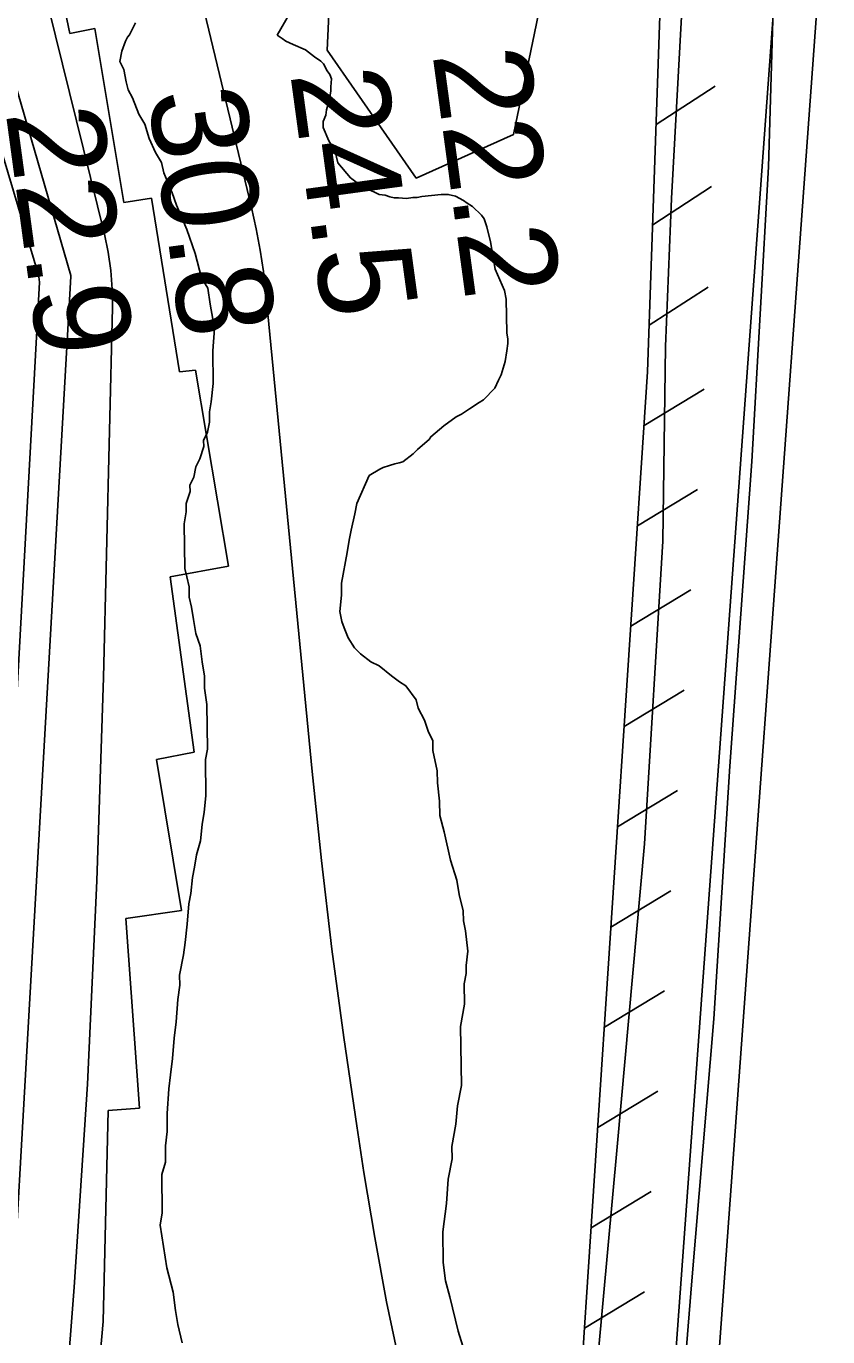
# Model space of a CAD drawing. Extents: x 3329297 to 3367176, y 649250 to 674653.
# Drawn here: x 3342831 to 3343389, y 663837 to 664750 of the extents above; entities that cross this region are included whole.
import ezdxf

# ---------------------------------------------------------------- set-up
doc = ezdxf.new("R2010")
doc.units = 0
for name, color, linetype in [('V-BORW-LINE', 7, 'Continuous'), ('V-FLOD-BASE', 7, 'Continuous'), ('V-LEVE-TOET', 7, 'Continuous'), ('V-RIVR-RANG', 7, 'Continuous'), ('V-RRAP-FSHR', 7, 'Continuous'), ('V-RRAP-RVMT', 7, 'Continuous'), ('V-SITE-VEGE', 7, 'Continuous'), ('V-SURV-LINE', 7, 'Continuous'), ('V-TOPO-MAJR', 7, 'Continuous'), ('V-TOPO-MINR', 7, 'Continuous'), ('V-UTIL-LINE', 7, 'Continuous')]:
    doc.layers.add(name, color=color, linetype=linetype)

msp = doc.modelspace()

# ---------------------------------------------------------------- linework, layer by layer
at = {"layer": 'V-BORW-LINE'}
msp.add_lwpolyline([(3343069.37, 665437.27), (3343157.84, 665121.27), (3343197, 664803.79), (3343170.32, 664674.7), (3343102.62, 664644.41), (3343040.65, 664733.52), (3343047.48, 664883.11), (3343014.8, 664992.94), (3342986.43, 665132.42), (3342882.8, 665383.73), (3342843.32, 665513.52), (3342834.44, 665645.06), (3342769.09, 665672.3), (3342730.55, 665756.83), (3342719.33, 665922.12), (3342776.61, 665949.79), (3342894.11, 665914.3), (3342956.7, 665801.76), (3343024.35, 665598.74), (3343056.3, 665505.31), (3343069.37, 665437.27)], dxfattribs=at)
at = {"layer": 'V-FLOD-BASE'}
msp.add_lwpolyline([(3343280.1, 663698.15), (3343294.63, 663876.34), (3343309.81, 664058.72), (3343320.9, 664234.79), (3343336.41, 664447.07), (3343347.84, 664652.35), (3343353.8, 664849.22)], dxfattribs=at)
at = {"layer": 'V-LEVE-TOET'}
msp.add_lwpolyline([(3343222.88, 663753.95), (3343242.52, 663969.76), (3343261.53, 664180.69), (3343274.28, 664391.55), (3343276.12, 664527.17), (3343280.43, 664630.14), (3343288.38, 664778.36)], dxfattribs=at)
at = {"layer": 'V-RRAP-FSHR'}
for p, q in [((3343269.72, 664681.79), (3343310.67, 664708.4)), ((3343267.3, 664611.83), (3343308.24, 664638.44)), ((3343264.87, 664541.88), (3343305.82, 664568.48)), ((3343261.27, 664471.98), (3343303.03, 664497.29)), ((3343256.66, 664402.13), (3343298.42, 664427.44)), ((3343252.06, 664332.28), (3343293.81, 664357.6)), ((3343247.45, 664262.43), (3343289.2, 664287.75)), ((3343242.84, 664192.59), (3343284.59, 664217.9)), ((3343238.23, 664122.74), (3343279.98, 664148.05)), ((3343233.62, 664052.89), (3343275.38, 664078.2)), ((3343229.01, 663983.04), (3343270.77, 664008.35)), ((3343224.4, 663913.19), (3343266.16, 663938.51)), ((3343219.79, 663843.35), (3343261.55, 663868.66))]:
    msp.add_line(p, q, dxfattribs=at)
msp.add_lwpolyline([(3342422.66, 666572.09), (3342506.32, 666419.51), (3342528.65, 666362.43), (3342544.71, 666298.95), (3342558.05, 666267.29), (3342572.99, 666237.96), (3342584.69, 666224.79), (3342612.1, 666200.12), (3342644.7, 666176.02), (3342965.69, 665990.52), (3342988.82, 665948.09), (3343214.8, 665141.21), (3343235.9, 665073.88), (3343259.54, 664966.24), (3343269.46, 664898.18), (3343274.9, 664831.38), (3343263.75, 664509.56), (3343214.47, 663762.74), (3343161.49, 663146), (3343150.56, 662991.8), (3343121.4, 662899.29), (3343057.2, 662738.8), (3342751.17, 661989.36), (3342644.16, 661768.69)], dxfattribs=at)
at = {"layer": 'V-RRAP-RVMT'}
for p, q in [((3342861.4, 664745.21), (3342833.32, 664876.95)), ((3342878.7, 664748.63), (3342861.4, 664745.21)), ((3342898.92, 664627.44), (3342878.7, 664748.63)), ((3342918.14, 664630.35), (3342898.92, 664627.44)), ((3342937.62, 664509.41), (3342918.14, 664630.35)), ((3342948.94, 664510.55), (3342937.62, 664509.41)), ((3342971.87, 664374.02), (3342948.94, 664510.55)), ((3342931.23, 664366.73), (3342971.87, 664374.02)), ((3342947.93, 664244.65), (3342931.23, 664366.73)), ((3342921.73, 664239.4), (3342947.93, 664244.65)), ((3342939.09, 664134.31), (3342921.73, 664239.4)), ((3342900.4, 664128.6), (3342939.09, 664134.31)), ((3342909.87, 663996.55), (3342900.4, 664128.6)), ((3342884.5, 663847.94), (3342887.98, 663994.85)), ((3342887.98, 663994.85), (3342909.87, 663996.55)), ((3342873.82, 663720.46), (3342884.5, 663847.94))]:
    msp.add_line(p, q, dxfattribs=at)
at = {"layer": 'V-SITE-VEGE'}
for points in [[(3343022.93, 664773.84), (3343005.64, 664744)], [(3342935.37, 664056.71), (3342936.59, 664072.3), (3342937.89, 664082.22), (3342937.8, 664089.29), (3342940.46, 664103.47), (3342941.77, 664111.98), (3342943.03, 664124.73), (3342944.28, 664138.9), (3342945.61, 664145.99), (3342946.89, 664157.33), (3342948.21, 664164.42), (3342949.53, 664172.93), (3342952.24, 664182.87), (3342953.51, 664194.2), (3342954.83, 664202.71), (3342956.1, 664214.05), (3342955.8, 664239.52), (3342957.13, 664246.61), (3342956.75, 664277.74), (3342955.2, 664289.04), (3342955.1, 664297.53), (3342953.56, 664307.41), (3342952.01, 664318.72), (3342949.08, 664327.17), (3342947.54, 664337.06), (3342946.02, 664345.53), (3342944.52, 664352.59), (3342944.44, 664359.67), (3342942.94, 664366.72), (3342941.45, 664372.37), (3342941.08, 664403.49), (3342942.39, 664412), (3342942.32, 664417.66), (3342945.05, 664426.19), (3342945, 664430.43), (3342947.76, 664436.12), (3342949.09, 664443.22), (3342951.85, 664448.91), (3342954.58, 664457.43), (3342954.53, 664461.68), (3342957.29, 664467.37), (3342958.62, 664474.46), (3342958.53, 664481.54), (3342959.86, 664488.63), (3342961.12, 664501.38), (3342960.85, 664524.02), (3342962.08, 664539.6), (3342959.04, 664556.55), (3342957.48, 664567.85), (3342953.16, 664574.88), (3342948.71, 664591.8), (3342942.85, 664608.71), (3342935.56, 664625.61), (3342932.63, 664634.06), (3342926.8, 664648.14), (3342925.3, 664655.2), (3342920.97, 664662.22), (3342916.6, 664672.08), (3342913.65, 664681.95), (3342909.32, 664688.97), (3342904.94, 664700.24), (3342902.04, 664705.86), (3342900.56, 664711.51), (3342899.04, 664719.98), (3342896.15, 664725.6), (3342897.48, 664732.7), (3342900.22, 664739.81), (3342901.6, 664742.65), (3342903, 664744.09), (3342907.14, 664752.63)], [(3343005.64, 664744), (3343009.32, 664741.6), (3343011.81, 664739.78), (3343016.79, 664737.36), (3343025.48, 664733.76), (3343031.71, 664728.9), (3343036.08, 664725.86), (3343037.95, 664724.03), (3343040.48, 664719.12), (3343042.37, 664716.67), (3343043.64, 664713.6), (3343043.09, 664708.03), (3343043.12, 664704.94), (3343041.97, 664698.13), (3343040.19, 664691.93), (3343039.62, 664688.22), (3343037.82, 664683.87), (3343037.87, 664679.55), (3343041.69, 664670.33), (3343046.1, 664662.97), (3343048.05, 664654.96), (3343056.83, 664644.56), (3343062.44, 664640.31), (3343064.31, 664639.1), (3343068.66, 664636.68), (3343073.01, 664634.88), (3343076.73, 664633.07), (3343081.07, 664632.5), (3343084.17, 664631.3), (3343087.27, 664630.72), (3343090.35, 664630.76), (3343095.92, 664630.21), (3343100.24, 664630.88), (3343103.33, 664630.92), (3343106.41, 664631.57), (3343119.98, 664632.97), (3343124.92, 664633.03), (3343129.88, 664631.86), (3343135.48, 664628.83), (3343137.97, 664627.01), (3343141.71, 664624.59), (3343147.96, 664618.48), (3343149.84, 664616.04), (3343151.76, 664610.5), (3343154.35, 664600.03), (3343157.68, 664580.92), (3343164.03, 664566.17), (3343165.34, 664560), (3343165.62, 664536.53), (3343166.29, 664532.22), (3343166.33, 664529.13), (3343165.77, 664524.18), (3343164.63, 664516.75), (3343161.65, 664507.45), (3343159.85, 664503.72), (3343157.44, 664498.13), (3343149.51, 664490.01), (3343146.44, 664488.11), (3343139.7, 664483.71), (3343134.19, 664479.94), (3343130.5, 664478.04), (3343121.93, 664471.76), (3343112.75, 664464.23), (3343111.54, 664462.37), (3343108.48, 664459.86), (3343103.59, 664455.47), (3343100.54, 664452.35), (3343093.2, 664446.7), (3343090.73, 664446.05), (3343087.65, 664445.4), (3343083.96, 664444.12), (3343079.65, 664442.83), (3343077.2, 664441.56), (3343069.84, 664437.15), (3343061.19, 664417.68), (3343059.87, 664410.59), (3343057.17, 664399.24), (3343055.84, 664392.14), (3343054.53, 664383.64), (3343050.54, 664362.36), (3343050.65, 664353.87), (3343049.37, 664342.54), (3343050.87, 664335.48), (3343052.33, 664331.25), (3343055.25, 664324.21), (3343059.58, 664317.19), (3343063.88, 664312.99), (3343071.02, 664307.42), (3343076.71, 664304.66), (3343085.29, 664297.69), (3343091, 664293.51), (3343095.28, 664290.73), (3343102.47, 664280.91), (3343103.95, 664275.27), (3343108.3, 664266.83), (3343111.23, 664258.38), (3343114.13, 664252.75), (3343114.22, 664245.68), (3343117.22, 664231.56), (3343117.32, 664223.07), (3343118.89, 664210.35)], [(3343118.89, 664210.35), (3343119.01, 664200.45), (3343121.98, 664189.16), (3343126.46, 664169.41), (3343130.88, 664155.31), (3343132.41, 664145.42), (3343135.38, 664134.14), (3343135.46, 664127.06), (3343136.97, 664120), (3343138.55, 664105.87), (3343137.26, 664095.95), (3343137.32, 664090.29), (3343136, 664083.2), (3343136.17, 664069.05), (3343133.52, 664053.45), (3343134.02, 664012.41), (3343131.36, 663998.23), (3343130.1, 663985.48), (3343127.46, 663969.88), (3343127.56, 663961.39), (3343124.9, 663947.21), (3343123.69, 663930.21), (3343121.1, 663910.37), (3343121.36, 663889.14), (3343122.93, 663876.43), (3343125.89, 663865.14), (3343131.85, 663841.15), (3343136.26, 663827.06)], [(3342939.48, 663833.17), (3342936.5, 663845.87), (3342934.96, 663855.76), (3342933.39, 663868.47), (3342928.94, 663885.4), (3342924.34, 663915.06), (3342925.65, 663923.57), (3342925.33, 663950.46), (3342928.06, 663958.98), (3342927.92, 663970.3), (3342929.21, 663980.22), (3342929.06, 663992.96), (3342930.27, 664009.95), (3342931.56, 664019.87), (3342932.84, 664031.21), (3342934.08, 664045.38), (3342935.37, 664056.71)]]:
    msp.add_lwpolyline(points, dxfattribs=at)
at = {"layer": 'V-SURV-LINE'}
for points in [[(3343219.54, 662949.27), (3343359.29, 664869.74)], [(3343389.21, 664867.57), (3343249.46, 662947.1)]]:
    msp.add_lwpolyline(points, dxfattribs=at)
at = {"layer": 'V-TOPO-MAJR'}
for points in [[(3342931.2, 664859.55), (3342987.87, 664623.95), (3342991.1, 664609.16), (3342993.92, 664594.3), (3342996.11, 664579.34), (3342997.88, 664564.3), (3343030.14, 664231.05), (3343036.66, 664169.2), (3343043.88, 664107.43), (3343052.16, 664045.8), (3343061.13, 663984.25), (3343066.15, 663951.7), (3343073.69, 663906.6), (3343081.97, 663861.65), (3343091.36, 663816.92)], [(3342853.37, 663730.49), (3342864.42, 663871.85), (3342873.66, 664013.3), (3342880.18, 664154.91), (3342884.89, 664296.61), (3342890.99, 664554.21), (3342890.78, 664567.14), (3342889.89, 664579.99), (3342887.98, 664592.73), (3342885.39, 664605.4), (3342841.6, 664783.22)]]:
    msp.add_lwpolyline(points, dxfattribs=at)
at = {"layer": 'V-TOPO-MINR'}
for points in [[(3342781.67, 663507.75), (3342840.16, 664572.02), (3342839.86, 664575.67), (3342839.73, 664576.18), (3342714.04, 664997.71), (3342681.72, 665105.22), (3342649.08, 665212.63), (3342615.94, 665319.89), (3342582.49, 665427.05), (3342527.81, 665600.81), (3342521.29, 665620.96), (3342514.57, 665641.05), (3342507.55, 665661.02), (3342500.32, 665680.93), (3342438.57, 665846.96), (3342399.38, 665949.45), (3342358.95, 666051.43), (3342316.65, 666152.66), (3342273.11, 666253.38), (3342138.95, 666556.06)], [(3342790.17, 663312.79), (3342862.06, 664575.94), (3342862.06, 664576.02), (3342862.06, 664576.17), (3342862.02, 664576.48), (3342862, 664576.56), (3342632.01, 665369.62), (3342618.1, 665417), (3342603.97, 665464.31), (3342589.53, 665511.54), (3342574.88, 665558.69), (3342567.67, 665581.62), (3342556.18, 665617.17), (3342544.32, 665652.59), (3342531.89, 665687.81), (3342519.08, 665722.9), (3342511.04, 665744.42), (3342493.52, 665790), (3342475.45, 665835.37), (3342456.57, 665880.4), (3342437.14, 665925.21), (3342160.51, 666547.74)]]:
    msp.add_lwpolyline(points, dxfattribs=at)
at = {"layer": 'V-UTIL-LINE'}
msp.add_lwpolyline([(3343214.47, 663762.74), (3343263.75, 664509.56), (3343274.9, 664831.38), (3343269.46, 664898.18), (3343259.54, 664966.24), (3343235.9, 665073.88), (3343214.8, 665141.21), (3342988.82, 665948.09), (3342965.69, 665990.52), (3342644.7, 666176.02), (3342612.1, 666200.12), (3342584.69, 666224.79), (3342572.99, 666237.96), (3342558.05, 666267.29), (3342544.71, 666298.95), (3342528.65, 666362.43), (3342506.32, 666419.51), (3342247.97, 666890.68), (3341998.18, 667355.34), (3341893.42, 667540.23), (3341355.82, 668355.57)], dxfattribs=at)

# ---------------------------------------------------------------- texts
at = {"layer": 'V-RIVR-RANG'}
for s, p in [('22.2', (3343113.86, 664730.85)), ('24.5', (3343014.81, 664717.14)), ('30.8', (3342915.75, 664703.43)), ('22.9', (3342816.66, 664689.99))]:
    msp.add_text(s, height=67, rotation=277.73833, dxfattribs=at).set_placement(p)

doc.saveas('drawing.dxf')
